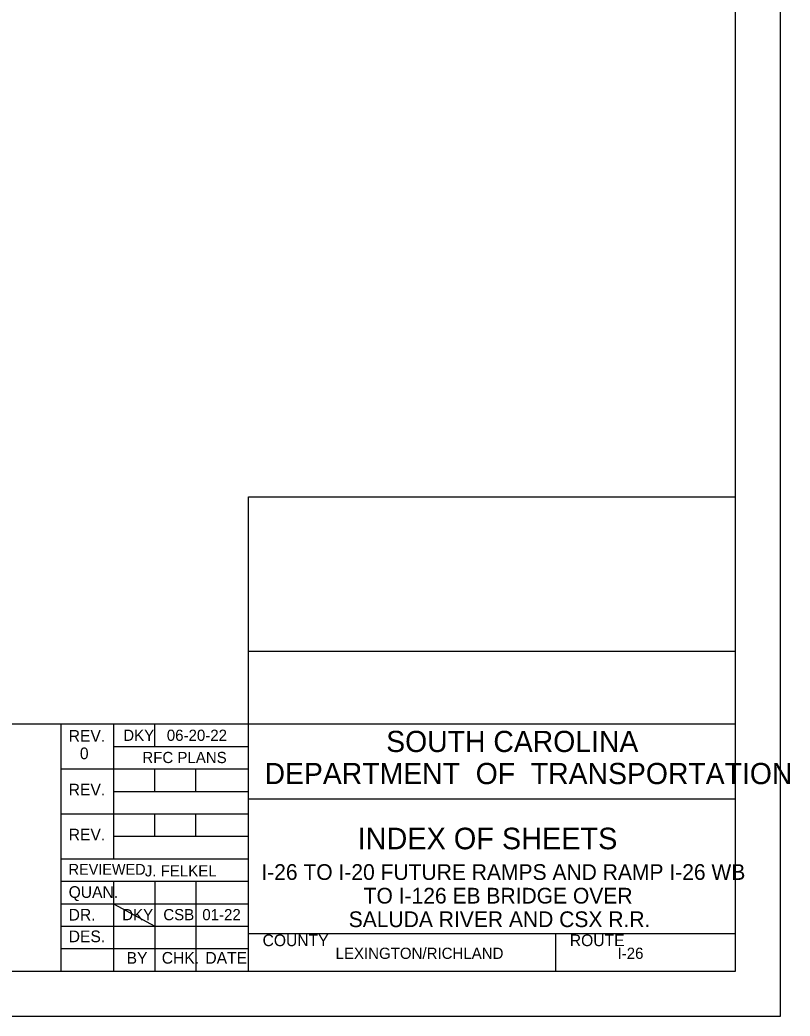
# Model space of a CAD drawing. Extents: x -125.5 to -89.4, y -5.1 to 16.9.
# Drawn here: x -97.99 to -89.43, y -5.07 to 6.02 of the extents above; entities that cross this region are included whole.
import ezdxf

# ---------------------------------------------------------------- set-up
doc = ezdxf.new("R2010")
doc.units = 0
for name, color, linetype in [('BR_BORDER LINES', 7, 'Continuous'), ('BR_TEXT', 7, 'Continuous'), ('Level 31', 7, 'Continuous')]:
    doc.layers.add(name, color=color, linetype=linetype)

msp = doc.modelspace()

# ---------------------------------------------------------------- linework, layer by layer
at = {"layer": 'BR_BORDER LINES'}
for p, q in [((-90.033, -4.566), (-90.033, 16.434)), ((-95.45, -4.566), (-95.45, 0.71)), ((-95.45, 0.71), (-90.033, 0.71)), ((-95.45, -1.004), (-90.033, -1.004)), ((-102.899, -1.816), (-97.534, -1.816)), ((-97.534, -4.566), (-97.534, -1.816)), ((-97.534, -1.816), (-90.033, -1.816)), ((-96.95, -1.816), (-96.95, -3.316)), ((-96.492, -2.066), (-96.492, -1.816)), ((-96.95, -2.066), (-95.45, -2.066)), ((-97.534, -2.316), (-95.45, -2.316)), ((-96.492, -2.566), (-96.492, -2.316)), ((-96.034, -2.566), (-96.034, -2.316)), ((-96.95, -2.566), (-95.45, -2.566)), ((-95.45, -2.649), (-95.45, -2.649)), ((-95.45, -2.649), (-90.033, -2.649)), ((-97.534, -2.816), (-95.45, -2.816)), ((-96.492, -3.066), (-96.492, -2.816)), ((-96.034, -3.066), (-96.034, -2.816)), ((-96.95, -3.066), (-95.45, -3.066)), ((-97.534, -3.316), (-95.45, -3.316)), ((-97.534, -3.566), (-95.45, -3.566)), ((-96.95, -3.566), (-96.95, -4.566)), ((-96.492, -3.566), (-96.492, -4.566)), ((-96.034, -3.566), (-96.034, -4.566)), ((-97.534, -3.816), (-95.45, -3.816)), ((-97.534, -4.066), (-95.45, -4.066)), ((-95.45, -4.149), (-90.033, -4.149)), ((-95.353, -4.149), (-90.033, -4.149)), ((-92.033, -4.566), (-92.033, -4.149)), ((-97.534, -4.316), (-95.45, -4.316)), ((-123.699, -4.566), (-90.033, -4.566))]:
    msp.add_line(p, q, dxfattribs=at)
at = {"layer": 'Level 31'}
for p, q in [((-92.742, -3.09), (-92.742, -3.09)), ((-96.95, -3.816), (-96.492, -4.066))]:
    msp.add_line(p, q, dxfattribs=at)
msp.add_lwpolyline([(-125.533, -5.066), (-89.533, -5.066), (-89.533, 16.934), (-125.533, 16.934)], close=True, dxfattribs=at)

# ---------------------------------------------------------------- texts
at = {"layer": 'BR_TEXT'}
for s, height, p in [('REV.', 0.13, (-97.449, -2.013)), ('DKY', 0.125, (-96.842, -2.004)), ('06-20-22', 0.125, (-96.358, -2.004)), ('SOUTH CAROLINA', 0.23587, (-93.918, -2.128)), ('0', 0.13, (-97.325, -2.208)), ('RFC PLANS', 0.125, (-96.63, -2.251)), ('DEPARTMENT  OF  TRANSPORTATION', 0.23587, (-95.271, -2.485)), ('REV.', 0.13, (-97.449, -2.611)), ('REV.', 0.13, (-97.449, -3.111)), ('INDEX OF SHEETS', 0.24, (-94.236, -3.21)), ('REVIEWED', 0.12, (-97.45, -3.493)), ('J. FELKEL', 0.125, (-96.603, -3.512)), ('I-26 TO I-20 FUTURE RAMPS AND RAMP I-26 WB', 0.175, (-95.307, -3.551)), ('QUAN.', 0.13, (-97.45, -3.751)), ('TO I-126 EB BRIDGE OVER', 0.175, (-94.169, -3.814)), ('DR.', 0.13, (-97.45, -4.003)), ('DKY', 0.125, (-96.854, -4)), ('CSB', 0.125, (-96.397, -4)), ('01-22', 0.125, (-95.963, -4)), ('SALUDA RIVER AND CSX R.R.', 0.175, (-94.335, -4.076)), ('DES.', 0.13, (-97.449, -4.244)), ('COUNTY', 0.13, (-95.293, -4.288)), ('ROUTE', 0.13, (-91.876, -4.288)), ('LEXINGTON/RICHLAND', 0.12499, (-94.481, -4.43)), ('I-26', 0.125, (-91.345, -4.43)), ('BY', 0.13, (-96.805, -4.484)), ('CHK.', 0.13, (-96.414, -4.483)), ('DATE', 0.13, (-95.929, -4.483))]:
    msp.add_text(s, height=height, dxfattribs=at).set_placement(p)

doc.saveas('drawing.dxf')
